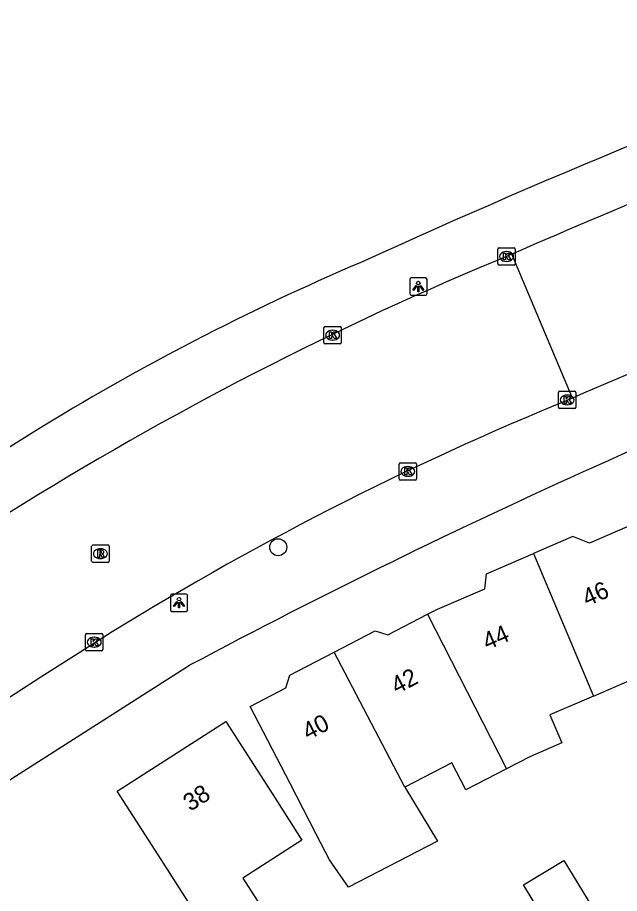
# Model space of a CAD drawing. Extents: x 160158 to 160921, y 381517 to 382041.
# Drawn here: x 160369 to 160403.6, y 381664.2 to 381714.5 of the extents above; entities that cross this region are included whole.
import ezdxf

# ---------------------------------------------------------------- set-up
doc = ezdxf.new("R2010")
doc.units = 0
for name, color, linetype in [('IMGEO_Boom', 7, 'Continuous'), ('IMGEO_Kolk', 7, 'Continuous'), ('IMGEO_Lichtpunt', 7, 'Continuous'), ('IMGEO_Muur', 7, 'Continuous'), ('IMGEO_Pand', 7, 'Continuous'), ('IMGEO_Pand_nummerreeks', 7, 'Continuous'), ('IMGEO_Rijbaan_lokaal_open', 7, 'Continuous'), ('IMGEO_Rioolput', 7, 'Continuous'), ('IMGEO_Voetpad_open', 7, 'Continuous')]:
    doc.layers.add(name, color=color, linetype=linetype)

msp = doc.modelspace()

# ---------------------------------------------------------------- linework, layer by layer
at = {"layer": 'IMGEO_Boom'}
msp.add_circle((160384.006, 381684.073), 0.489, dxfattribs=at)
at = {"layer": 'IMGEO_Kolk'}
for p, q in [((160396.646, 381700.37), (160396.646, 381701.222)), ((160396.721, 381701.296), (160397.573, 381701.296)), ((160397.134, 381701.076), (160397.159, 381701.076)), ((160397.647, 381701.222), (160397.647, 381700.37)), ((160397.157, 381700.516), (160397.132, 381700.516)), ((160397.573, 381700.296), (160396.721, 381700.296)), ((160386.636, 381695.844), (160386.636, 381696.696)), ((160386.711, 381696.77), (160387.563, 381696.77)), ((160387.124, 381696.55), (160387.149, 381696.55)), ((160387.637, 381696.696), (160387.637, 381695.844)), ((160387.147, 381695.99), (160387.122, 381695.99)), ((160387.563, 381695.77), (160386.711, 381695.77)), ((160400.132, 381692.121), (160400.132, 381692.973)), ((160400.207, 381693.047), (160401.059, 381693.047)), ((160401.133, 381692.973), (160401.133, 381692.121)), ((160400.62, 381692.827), (160400.645, 381692.827)), ((160401.059, 381692.047), (160400.207, 381692.047)), ((160400.643, 381692.267), (160400.618, 381692.267)), ((160390.966, 381688.008), (160390.966, 381688.86)), ((160391.041, 381688.934), (160391.893, 381688.934)), ((160391.967, 381688.86), (160391.967, 381688.008)), ((160391.454, 381688.714), (160391.479, 381688.714)), ((160391.893, 381687.934), (160391.041, 381687.934)), ((160391.477, 381688.154), (160391.452, 381688.154)), ((160372.922, 381678.189), (160372.922, 381679.041)), ((160372.997, 381679.115), (160373.849, 381679.115)), ((160373.41, 381678.895), (160373.435, 381678.895)), ((160373.923, 381679.041), (160373.923, 381678.189)), ((160373.433, 381678.335), (160373.408, 381678.335)), ((160373.849, 381678.115), (160372.997, 381678.115))]:
    msp.add_line(p, q, dxfattribs=at)
for points in [[(160396.646, 381700.37), (160396.646, 381701.222)], [(160396.721, 381701.296), (160397.573, 381701.296)], [(160396.967, 381700.996), (160397.09, 381700.996), (160397.09, 381700.845), (160397.22, 381700.996), (160397.384, 381700.996), (160397.238, 381700.845), (160397.391, 381700.596), (160397.239, 381700.596), (160397.154, 381700.76), (160397.09, 381700.693), (160397.09, 381700.596), (160396.967, 381700.596), (160396.967, 381700.996)], [(160397.647, 381701.222), (160397.647, 381700.37)], [(160397.573, 381700.296), (160396.721, 381700.296)], [(160386.636, 381695.844), (160386.636, 381696.696)], [(160386.711, 381696.77), (160387.563, 381696.77)], [(160386.957, 381696.47), (160387.08, 381696.47), (160387.08, 381696.319), (160387.21, 381696.47), (160387.374, 381696.47), (160387.228, 381696.319), (160387.381, 381696.07), (160387.229, 381696.07), (160387.144, 381696.234), (160387.08, 381696.167), (160387.08, 381696.07), (160386.957, 381696.07), (160386.957, 381696.47)], [(160387.637, 381696.696), (160387.637, 381695.844)], [(160387.563, 381695.77), (160386.711, 381695.77)], [(160400.132, 381692.121), (160400.132, 381692.973)], [(160400.207, 381693.047), (160401.059, 381693.047)], [(160401.133, 381692.973), (160401.133, 381692.121)], [(160400.453, 381692.747), (160400.576, 381692.747), (160400.576, 381692.596), (160400.706, 381692.747), (160400.87, 381692.747), (160400.724, 381692.596), (160400.877, 381692.347), (160400.725, 381692.347), (160400.64, 381692.511), (160400.576, 381692.444), (160400.576, 381692.347), (160400.453, 381692.347), (160400.453, 381692.747)], [(160401.059, 381692.047), (160400.207, 381692.047)], [(160390.966, 381688.008), (160390.966, 381688.86)], [(160391.041, 381688.934), (160391.893, 381688.934)], [(160391.967, 381688.86), (160391.967, 381688.008)], [(160391.287, 381688.634), (160391.41, 381688.634), (160391.41, 381688.483), (160391.54, 381688.634), (160391.704, 381688.634), (160391.558, 381688.483), (160391.711, 381688.234), (160391.559, 381688.234), (160391.474, 381688.398), (160391.41, 381688.331), (160391.41, 381688.234), (160391.287, 381688.234), (160391.287, 381688.634)], [(160391.893, 381687.934), (160391.041, 381687.934)], [(160372.922, 381678.189), (160372.922, 381679.041)], [(160372.997, 381679.115), (160373.849, 381679.115)], [(160373.243, 381678.815), (160373.366, 381678.815), (160373.366, 381678.664), (160373.496, 381678.815), (160373.66, 381678.815), (160373.514, 381678.664), (160373.667, 381678.415), (160373.515, 381678.415), (160373.43, 381678.579), (160373.366, 381678.512), (160373.366, 381678.415), (160373.243, 381678.415), (160373.243, 381678.815)], [(160373.923, 381679.041), (160373.923, 381678.189)], [(160373.849, 381678.115), (160372.997, 381678.115)]]:
    msp.add_lwpolyline(points, dxfattribs=at)
for centre, start, end in [((160396.723, 381701.22), 91.552, 178.448), ((160396.723, 381701.22), 91.552, 178.448), ((160397.571, 381701.22), 1.552, 88.448), ((160397.571, 381701.22), 1.552, 88.448), ((160396.723, 381700.372), 181.552, 268.448), ((160396.723, 381700.372), 181.552, 268.448), ((160397.571, 381700.372), 271.552, 358.448), ((160397.571, 381700.372), 271.552, 358.448), ((160386.713, 381696.694), 91.552, 178.448), ((160386.713, 381696.694), 91.552, 178.448), ((160387.561, 381696.694), 1.552, 88.448), ((160387.561, 381696.694), 1.552, 88.448), ((160386.713, 381695.846), 181.552, 268.448), ((160386.713, 381695.846), 181.552, 268.448), ((160387.561, 381695.846), 271.552, 358.448), ((160387.561, 381695.846), 271.552, 358.448), ((160400.209, 381692.971), 91.552, 178.448), ((160400.209, 381692.971), 91.552, 178.448), ((160401.057, 381692.971), 1.552, 88.448), ((160401.057, 381692.971), 1.552, 88.448), ((160400.209, 381692.123), 181.552, 268.448), ((160400.209, 381692.123), 181.552, 268.448), ((160401.057, 381692.123), 271.552, 358.448), ((160401.057, 381692.123), 271.552, 358.448), ((160391.043, 381688.858), 91.552, 178.448), ((160391.043, 381688.858), 91.552, 178.448), ((160391.891, 381688.858), 1.552, 88.448), ((160391.891, 381688.858), 1.552, 88.448), ((160391.043, 381688.01), 181.552, 268.448), ((160391.043, 381688.01), 181.552, 268.448), ((160391.891, 381688.01), 271.552, 358.448), ((160391.891, 381688.01), 271.552, 358.448), ((160372.999, 381679.039), 91.552, 178.448), ((160372.999, 381679.039), 91.552, 178.448), ((160373.847, 381679.039), 1.552, 88.448), ((160373.847, 381679.039), 1.552, 88.448), ((160372.999, 381678.191), 181.552, 268.448), ((160372.999, 381678.191), 181.552, 268.448), ((160373.847, 381678.191), 271.552, 358.448), ((160373.847, 381678.191), 271.552, 358.448)]:
    msp.add_arc(centre, 0.0765, start, end, dxfattribs=at)
for centre, major_axis, ratio, start_param, end_param in [((160397.133, 381700.796), (-0.387, 0.002), 0.722429, 4.712389, 7.853982), ((160397.158, 381700.796), (-0.39, 0.002), 0.717154, 1.570796, 4.712389), ((160387.123, 381696.27), (-0.387, 0.002), 0.722429, 4.712389, 7.853982), ((160387.148, 381696.27), (-0.39, 0.002), 0.717154, 1.570796, 4.712389), ((160400.619, 381692.547), (-0.387, 0.002), 0.722429, 4.712389, 7.853982), ((160400.644, 381692.547), (-0.39, 0.002), 0.717154, 1.570796, 4.712389), ((160391.453, 381688.434), (-0.387, 0.002), 0.722429, 4.712389, 7.853982), ((160391.478, 381688.434), (-0.39, 0.002), 0.717154, 1.570796, 4.712389), ((160373.409, 381678.615), (-0.387, 0.002), 0.722429, 4.712389, 7.853982), ((160373.434, 381678.615), (-0.39, 0.002), 0.717154, 1.570796, 4.712389)]:
    msp.add_ellipse(centre, major_axis=major_axis, ratio=ratio, start_param=start_param, end_param=end_param, dxfattribs=at)
at = {"layer": 'IMGEO_Lichtpunt'}
for p, q in [((160391.571, 381699.47), (160391.571, 381698.663)), ((160391.571, 381699.47), (160391.571, 381698.663)), ((160392.473, 381699.565), (160391.665, 381699.565)), ((160392.473, 381699.565), (160391.665, 381699.565)), ((160392.567, 381698.663), (160392.567, 381699.47)), ((160392.567, 381698.663), (160392.567, 381699.47)), ((160391.665, 381698.569), (160392.473, 381698.569)), ((160391.665, 381698.569), (160392.473, 381698.569)), ((160377.799, 381681.29), (160377.799, 381680.483)), ((160377.799, 381681.29), (160377.799, 381680.483)), ((160378.701, 381681.385), (160377.893, 381681.385)), ((160378.701, 381681.385), (160377.893, 381681.385)), ((160378.795, 381680.483), (160378.795, 381681.29)), ((160378.795, 381680.483), (160378.795, 381681.29)), ((160377.893, 381680.389), (160378.701, 381680.389)), ((160377.893, 381680.389), (160378.701, 381680.389))]:
    msp.add_line(p, q, dxfattribs=at)
for points in [[(160391.945, 381699.134), (160391.984, 381699.106), (160391.796, 381698.844), (160391.758, 381698.871), (160391.945, 381699.134)], [(160392.047, 381699.086), (160392.094, 381699.086), (160392.094, 381698.764), (160392.047, 381698.764), (160392.047, 381699.086)], [(160392.157, 381699.106), (160392.195, 381699.133), (160392.382, 381698.871), (160392.343, 381698.843), (160392.157, 381699.106)], [(160378.173, 381680.954), (160378.212, 381680.926), (160378.024, 381680.664), (160377.986, 381680.691), (160378.173, 381680.954)], [(160378.275, 381680.906), (160378.322, 381680.906), (160378.322, 381680.584), (160378.275, 381680.584), (160378.275, 381680.906)], [(160378.385, 381680.926), (160378.423, 381680.953), (160378.61, 381680.691), (160378.571, 381680.663), (160378.385, 381680.926)]]:
    msp.add_lwpolyline(points, dxfattribs=at)
for centre in [(160392.07, 381699.268), (160378.298, 381681.088)]:
    msp.add_circle(centre, 0.0994, dxfattribs=at)
for centre, start, end in [((160391.665, 381699.47), 90, 180), ((160391.665, 381699.47), 90, 180), ((160392.473, 381699.47), 0, 90), ((160392.473, 381699.47), 0, 90), ((160391.665, 381698.663), 180, 270), ((160391.665, 381698.663), 180, 270), ((160392.473, 381698.663), 270, 0), ((160392.473, 381698.663), 270, 360), ((160377.893, 381681.29), 90, 180), ((160377.893, 381681.29), 90, 180), ((160378.701, 381681.29), 0, 90), ((160378.701, 381681.29), 0, 90), ((160377.893, 381680.483), 180, 270), ((160377.893, 381680.483), 180, 270), ((160378.701, 381680.483), 270, 0), ((160378.701, 381680.483), 270, 360)]:
    msp.add_arc(centre, 0.0946, start, end, dxfattribs=at)
at = {"layer": 'IMGEO_Muur'}
msp.add_lwpolyline([(160369.922, 381690.69), (160360.83, 381685.003), (160360.513, 381685.494)], dxfattribs=at)
for centre, radius, start, end in [((160579.399, 381282.334), 459.531, 109.85873, 114.51032), ((160444.129, 381570.593), 141.173, 113.09229, 121.71168)]:
    msp.add_arc(centre, radius, start, end, dxfattribs=at)
at = {"layer": 'IMGEO_Pand'}
for points in [[(160402.154, 381675.519), (160404.795, 381676.658), (160405.472, 381675.087), (160407.999, 381676.177), (160407.358, 381677.662), (160406.067, 381680.656), (160404.088, 381685.247), (160401.91, 381684.308), (160400.952, 381684.688), (160398.688, 381683.712)], [(160392.603, 381680.222), (160393.177, 381680.519), (160395.894, 381681.69), (160395.995, 381682.551), (160398.688, 381683.712)], [(160398.688, 381683.712), (160402.154, 381675.519)], [(160387.224, 381678.047), (160389.588, 381679.27), (160390.317, 381679.038), (160392.603, 381680.222)], [(160392.603, 381680.222), (160397.149, 381671.333)], [(160391.285, 381670.281), (160393.17, 381667.17), (160388.045, 381664.518), (160386.959, 381666.105), (160386.196, 381667.571), (160384.688, 381670.486), (160382.39, 381674.926), (160384.436, 381675.985), (160384.672, 381676.726), (160387.224, 381678.047)], [(160391.285, 381670.281), (160387.224, 381678.047)], [(160402.154, 381675.519), (160399.631, 381674.432), (160400.327, 381672.818), (160398.478, 381672.021), (160397.149, 381671.333)], [(160377.44, 381665.847), (160374.741, 381670.056), (160380.99, 381674.063), (160383.689, 381669.854), (160385.368, 381667.234), (160381.962, 381665.051), (160384.166, 381661.614), (160381.323, 381659.791), (160377.44, 381665.847)], [(160397.149, 381671.333), (160394.803, 381670.119), (160393.994, 381671.683), (160391.285, 381670.281)], [(160398.115, 381664.662), (160400.433, 381666.068), (160402.314, 381662.966), (160399.997, 381661.56), (160398.115, 381664.662)]]:
    msp.add_lwpolyline(points, dxfattribs=at)
at = {"layer": 'IMGEO_Rijbaan_lokaal_open'}
for points in [[(160400.944, 381692.654), (160397.446, 381700.927)], [(160373.638, 381678.699), (160370.346, 381676.606), (160367.056, 381674.482), (160362.994, 381671.837), (160355.653, 381667.141), (160331.601, 381651.639), (160328.02, 381649.339), (160318.701, 381643.354)]]:
    msp.add_lwpolyline(points, dxfattribs=at)
for centre, radius, start, end in [((160608.825, 381216.645), 528.403, 111.17271, 113.58026), ((160471.377, 381521.604), 193.965, 112.40538, 122.03846), ((160659.5, 381094.633), 651.521, 111.444808, 113.381413), ((160468.785, 381526.216), 179.733, 112.17602, 121.96348)]:
    msp.add_arc(centre, radius, start, end, dxfattribs=at)
at = {"layer": 'IMGEO_Rioolput'}
for p, q in [((160373.271, 381683.28), (160373.271, 381684.132)), ((160373.346, 381684.206), (160374.198, 381684.206)), ((160373.759, 381683.986), (160373.784, 381683.986)), ((160374.272, 381684.132), (160374.272, 381683.28)), ((160373.782, 381683.426), (160373.757, 381683.426)), ((160374.198, 381683.206), (160373.346, 381683.206))]:
    msp.add_line(p, q, dxfattribs=at)
for points in [[(160373.271, 381683.28), (160373.271, 381684.132)], [(160373.346, 381684.206), (160374.198, 381684.206)], [(160373.86, 381683.904), (160373.608, 381683.906), (160373.608, 381683.506)], [(160373.786, 381683.825), (160373.732, 381683.825), (160373.732, 381683.744)], [(160374.272, 381684.132), (160374.272, 381683.28)], [(160373.608, 381683.506), (160373.732, 381683.506), (160373.732, 381683.668), (160373.743, 381683.668)], [(160373.732, 381683.744), (160373.784, 381683.744)], [(160373.79, 381683.639), (160373.861, 381683.506), (160374.001, 381683.506), (160373.936, 381683.632)], [(160374.198, 381683.206), (160373.346, 381683.206)]]:
    msp.add_lwpolyline(points, dxfattribs=at)
for centre, radius, start, end in [((160373.348, 381684.13), 0.0765, 91.552, 178.448), ((160373.348, 381684.13), 0.0765, 91.552, 178.448), ((160373.792, 381683.729), 0.0964, 77.0061, 93.1865), ((160373.806, 381683.786), 0.0378, 276.6634, 79.6772), ((160373.859, 381683.794), 0.109, 350.3612, 89.416), ((160374.196, 381684.13), 0.0765, 1.552, 88.448), ((160374.196, 381684.13), 0.0765, 1.552, 88.448), ((160373.742, 381683.615), 0.0533, 26.0293, 88.6989), ((160373.768, 381683.933), 0.19, 274.7715, 282.9687), ((160373.857, 381683.794), 0.112, 277.5842, 350.9817), ((160373.841, 381683.579), 0.108, 29.5134, 73.7905), ((160373.348, 381683.282), 0.0765, 181.552, 268.448), ((160373.348, 381683.282), 0.0765, 181.552, 268.448), ((160374.196, 381683.282), 0.0765, 271.552, 358.448), ((160374.196, 381683.282), 0.0765, 271.552, 358.448)]:
    msp.add_arc(centre, radius, start, end, dxfattribs=at)
for centre, major_axis, ratio, start_param, end_param in [((160373.758, 381683.706), (-0.387, 0.002), 0.722429, 4.712389, 7.853982), ((160373.783, 381683.706), (-0.39, 0.002), 0.717154, 1.570796, 4.712389)]:
    msp.add_ellipse(centre, major_axis=major_axis, ratio=ratio, start_param=start_param, end_param=end_param, dxfattribs=at)
at = {"layer": 'IMGEO_Voetpad_open'}
for points in [[(160369.922, 381690.69), (160360.83, 381685.003), (160360.513, 381685.494), (160355.37, 381682.336), (160355.613, 381681.967), (160335.072, 381668.419), (160315.003, 381655.51), (160303.442, 381648.074), (160293.877, 381642.708), (160287.207, 381639.31), (160282.085, 381637.13), (160274.895, 381634.961), (160273.476, 381634.643)], [(160319.993, 381639.498), (160355.248, 381662.223), (160378.904, 381677.285)]]:
    msp.add_lwpolyline(points, dxfattribs=at)
for centre, radius, start, end in [((160579.399, 381282.334), 459.531, 109.85873, 114.51032), ((160444.129, 381570.593), 141.173, 113.09229, 121.71168), ((160563.843, 381329.278), 394.096, 110.4133, 117.98729)]:
    msp.add_arc(centre, radius, start, end, dxfattribs=at)

# ---------------------------------------------------------------- texts
at = {"layer": 'IMGEO_Pand_nummerreeks'}
for s, rotation, p in [('46', 23.6316, (160401.774, 381680.655)), ('44', 23.6316, (160396.032, 381678.142)), ('42', 27.4082, (160390.824, 381675.604)), ('40', 27.4082, (160385.722, 381672.96)), ('38', 32.6689, (160378.943, 381668.854))]:
    msp.add_text(s, height=1, rotation=rotation, dxfattribs=at).set_placement(p)

doc.saveas('drawing.dxf')
